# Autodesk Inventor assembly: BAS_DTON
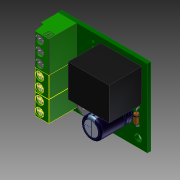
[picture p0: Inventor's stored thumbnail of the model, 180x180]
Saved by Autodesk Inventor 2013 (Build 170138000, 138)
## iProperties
Created: 2021-02
Part Number: BAS_DTON
Document SubType Name: Assembly
Designer: Fede
Translation Standard: STEP AP214IS
FileName: Open CASCADE Shape Model
PreProcessor: Open CASCADE 6.2
PostProcessor: Build: 138, Release: 2013 RTM - Date: Thu 03/01/2012
Sent Units: millimeter
Uncertainty: 0.0001
Author: Fede
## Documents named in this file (16)
- C:\0000 FEDE\16GB\0000 INTERIOR\DE_TMP_BAS\BAS_DTON - demora conexion al energizar\DTON_MANUAL\img\INVENTOR\BAS_DTON - SIN R\BAS_DTON_SIN R.iam
- C:\0000 FEDE\16GB\0000 INTERIOR\DE_TMP_BAS\BAS_DTON - demora conexion al energizar\DTON_MANUAL\img\INVENTOR\BAS_DTON - SIN R\Board.ipt
- C:\0000 FEDE\16GB\0000 INTERIOR\DE_TMP_BAS\BAS_DTON - demora conexion al energizar\DTON_MANUAL\img\INVENTOR\BAS_DTON - SIN R\JP4.iam
- C:\0000 FEDE\16GB\0000 INTERIOR\DE_TMP_BAS\BAS_DTON - demora conexion al energizar\DTON_MANUAL\img\INVENTOR\BAS_DTON - SIN R\JP3.iam
- C:\0000 FEDE\16GB\0000 INTERIOR\DE_TMP_BAS\BAS_DTON - demora conexion al energizar\DTON_MANUAL\img\INVENTOR\BAS_DTON - SIN R\JP2.iam
- C:\0000 FEDE\16GB\0000 INTERIOR\DE_TMP_BAS\BAS_DTON - demora conexion al energizar\DTON_MANUAL\img\INVENTOR\BAS_DTON - SIN R\R2.iam
- C:\0000 FEDE\16GB\0000 INTERIOR\DE_TMP_BAS\BAS_DTON - demora conexion al energizar\DTON_MANUAL\img\INVENTOR\BAS_DTON - SIN R\R8.iam
- C:\0000 FEDE\16GB\0000 INTERIOR\DE_TMP_BAS\BAS_DTON - demora conexion al energizar\DTON_MANUAL\img\INVENTOR\BAS_DTON - SIN R\D2.iam
- C:\0000 FEDE\16GB\0000 INTERIOR\DE_TMP_BAS\BAS_DTON - demora conexion al energizar\DTON_MANUAL\img\INVENTOR\BAS_DTON - SIN R\R7.iam
- C:\0000 FEDE\16GB\0000 INTERIOR\DE_TMP_BAS\BAS_DTON - demora conexion al energizar\DTON_MANUAL\img\INVENTOR\BAS_DTON - SIN R\Q1.iam
- C:\0000 FEDE\16GB\0000 INTERIOR\DE_TMP_BAS\BAS_DTON - demora conexion al energizar\DTON_MANUAL\img\INVENTOR\BAS_DTON - SIN R\C3.iam
- C:\0000 FEDE\16GB\0000 INTERIOR\DE_TMP_BAS\BAS_DTON - demora conexion al energizar\DTON_MANUAL\img\INVENTOR\BAS_DTON - SIN R\R1.iam
- C:\0000 FEDE\16GB\0000 INTERIOR\DE_TMP_BAS\BAS_DTON - demora conexion al energizar\DTON_MANUAL\img\INVENTOR\BAS_DTON - SIN R\K1.iam
- C:\0000 FEDE\16GB\0000 INTERIOR\DE_TMP_BAS\BAS_DTON - demora conexion al energizar\DTON_MANUAL\img\INVENTOR\BAS_DTON - SIN R\R5.iam
- C:\0000 FEDE\16GB\0000 INTERIOR\DE_TMP_BAS\BAS_DTON - demora conexion al energizar\DTON_MANUAL\img\INVENTOR\BAS_DTON - SIN R\D3.iam
- C:\0000 FEDE\16GB\0000 INTERIOR\DE_TMP_BAS\BAS_DTON - demora conexion al energizar\DTON_MANUAL\img\INVENTOR\BAS_DTON - SIN R\Free-Models.iam
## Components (15 placed, 15 different names)
1. Board:1
2. JP4:1 [sub-assembly]
3. JP3:1 [sub-assembly]
4. JP2:1 [sub-assembly]
5. R2:1 [sub-assembly]
6. R8:1 [sub-assembly]
7. D2:1 [sub-assembly]
8. R7:1 [sub-assembly]
9. Q1:1 [sub-assembly]
10. C3:1 [sub-assembly]
11. R1:1 [sub-assembly]
12. K1:1 [sub-assembly]
13. R5:1 [sub-assembly]
14. D3:1 [sub-assembly]
15. Free-Models:1 [sub-assembly]
